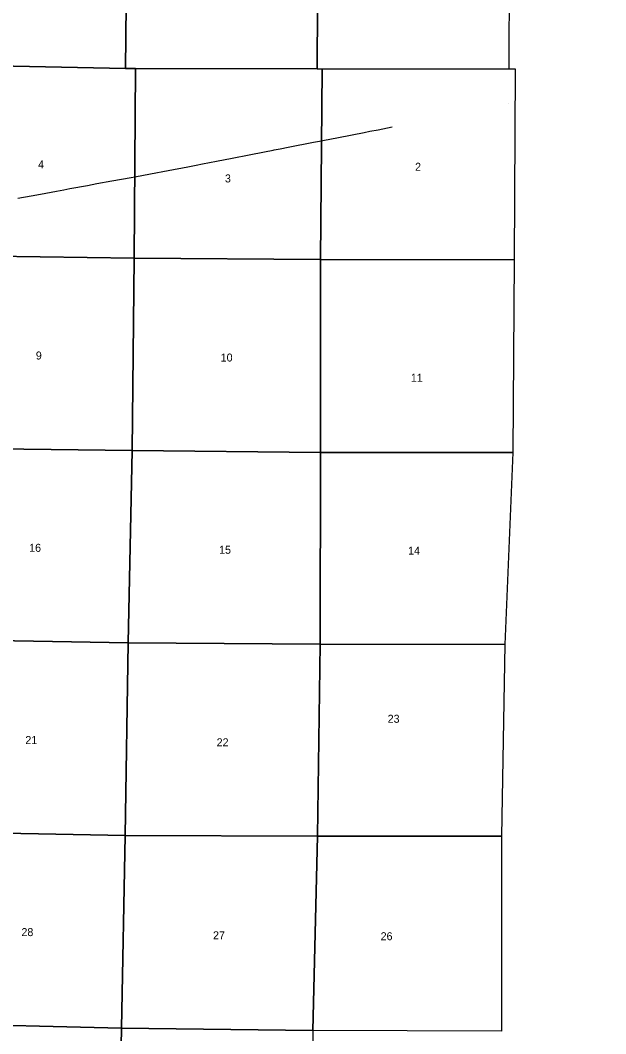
# Model space of a CAD drawing. Extents: x 1587405 to 1714697, y 1028970 to 1155083.
# Drawn here: x 1695754 to 1711915, y 1096415 to 1124403 of the extents above; entities that cross this region are included whole.
import ezdxf

# ---------------------------------------------------------------- set-up
doc = ezdxf.new("R2010")
doc.units = 0
for name, color, linetype in [('GM_X_Section', 7, 'Continuous'), ('GM_X_Section_Text', 7, 'Continuous'), ('GM_X_Unincorporated_Location', 7, 'Continuous'), ('GM_X_US_Location', 7, 'Continuous'), ('GM_X_US_Route', 7, 'Continuous')]:
    doc.layers.add(name, color=color, linetype=linetype)

msp = doc.modelspace()

# ---------------------------------------------------------------- linework, layer by layer
at = {"layer": 'GM_X_Section'}
for points in [[(1693423, 1128497), (1698713, 1128358), (1698662, 1123069), (1693792, 1123177), (1693370, 1123188)], [(1698713, 1128358), (1703978, 1128334), (1703954, 1123061), (1698938, 1123070), (1698662, 1123069)], [(1703978, 1128334), (1709254, 1128334), (1709239, 1123064), (1704090, 1123055), (1703954, 1123061)], [(1698662, 1123069), (1698938, 1123070), (1698898, 1117833), (1693702, 1117905), (1693792, 1123177)], [(1698938, 1123070), (1703954, 1123061), (1704090, 1123055), (1704037, 1117794), (1698898, 1117833)], [(1709239, 1123064), (1709419, 1123064), (1709389, 1117783), (1704037, 1117794), (1704090, 1123055)], [(1698898, 1117833), (1698839, 1112524), (1693611, 1112588), (1693702, 1117905)], [(1704037, 1117794), (1704044, 1112470), (1698839, 1112524), (1698898, 1117833)], [(1709389, 1117783), (1709354, 1112471), (1704044, 1112470), (1704037, 1117794)], [(1693611, 1112588), (1698839, 1112524), (1698736, 1107208), (1693496, 1107302)], [(1698839, 1112524), (1704044, 1112470), (1704032, 1107173), (1698736, 1107208)], [(1704044, 1112470), (1709354, 1112471), (1709133, 1107168), (1704032, 1107173)], [(1698736, 1107208), (1698653, 1101893), (1693371, 1101990), (1693496, 1107302)], [(1704032, 1107173), (1703959, 1101868), (1698653, 1101893), (1698736, 1107208)], [(1709133, 1107168), (1709042, 1101874), (1703959, 1101868), (1704032, 1107173)], [(1693371, 1101990), (1698653, 1101893), (1698546, 1096565), (1693264, 1096696)], [(1698653, 1101893), (1703959, 1101868), (1703829, 1096500), (1698546, 1096565)], [(1703959, 1101868), (1709042, 1101874), (1709038, 1096482), (1703829, 1096500)], [(1698546, 1096565), (1698444, 1091265), (1693788, 1091391), (1693172, 1091402), (1693264, 1096696)], [(1703829, 1096500), (1703766, 1091193), (1698802, 1091266), (1698444, 1091265), (1698546, 1096565)]]:
    msp.add_lwpolyline(points, close=True, dxfattribs=at)
at = {"layer": 'GM_X_Unincorporated_Location'}
msp.add_line((1709229, 1122099), (1709229, 1122099), dxfattribs=at)
at = {"layer": 'GM_X_US_Route'}
msp.add_lwpolyline([(1695685, 1119492), (1696057, 1119556), (1696315, 1119604), (1696751, 1119684), (1696961, 1119723), (1697122, 1119753), (1697606, 1119844), (1697865, 1119891), (1698285, 1119968), (1698817, 1120065), (1698912, 1120082), (1699350, 1120161), (1699834, 1120251), (1700382, 1120357), (1700608, 1120399), (1700785, 1120435), (1701172, 1120511), (1701606, 1120598), (1702073, 1120689), (1702492, 1120772), (1702734, 1120818), (1702762, 1120823), (1702927, 1120856), (1703153, 1120899), (1703845, 1121035), (1704069, 1121076), (1704104, 1121082), (1704539, 1121168), (1705247, 1121306), (1705407, 1121337), (1705634, 1121381), (1706019, 1121457)], dxfattribs=at)

# ---------------------------------------------------------------- texts
at = {"layer": 'GM_X_Section_Text'}
for s, p in [('4', (1696246, 1120312)), ('2', (1706652, 1120246)), ('3', (1701403, 1119925)), ('9', (1696184, 1115035)), ('10', (1701286, 1114978)), ('11', (1706535, 1114421)), ('16', (1695999, 1109724)), ('15', (1701242, 1109670)), ('14', (1706460, 1109646)), ('23', (1705895, 1105003)), ('21', (1695894, 1104415)), ('22', (1701174, 1104353)), ('28', (1695786, 1099111)), ('27', (1701075, 1099023)), ('26', (1705701, 1098997))]:
    msp.add_text(s, height=221, rotation=0, dxfattribs=at).set_placement(p)
at = {"layer": 'GM_X_US_Location'}
for s in ['0', '/']:
    msp.add_text(s, height=1, dxfattribs=at).set_placement((1711914, 1122389))
msp.add_text('224', height=1, rotation=0, dxfattribs=at).set_placement((1711606, 1122182))

doc.saveas('drawing.dxf')
